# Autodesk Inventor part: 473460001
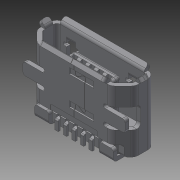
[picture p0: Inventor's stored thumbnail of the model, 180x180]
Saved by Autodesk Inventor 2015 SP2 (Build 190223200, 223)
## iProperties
Created: 2014-11
Part Number: 473460001
Material: Allgemein
Document SubType Name: Modeling
Designer: rYan
Density: 1 g/cm^3
Appearance: Vorgabe
Mass: 0.0444017 g
Surface Area: 2.57911 cm^2
Volume: 0.0444017 cm^3
Übersetzungsnorm: STEP AP203
Dateiname: 473460001
Vorprozessor: PRO/ENGINEER BY PARAMETRIC TECHNOLOGY CORPORATION, 2011490
Postprozessor: Build: 200, Release: 2013 SP2 Update 1 - Date: Fri 06/14/2013
Gesendete Einheiten: Millimeter
Unbestimmtheit: 0.0010537533691410003
Author: rYan
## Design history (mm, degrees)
node "4734600011"
  sketch "3D-Skizze1"
node "473460001"
node "Basis1"
